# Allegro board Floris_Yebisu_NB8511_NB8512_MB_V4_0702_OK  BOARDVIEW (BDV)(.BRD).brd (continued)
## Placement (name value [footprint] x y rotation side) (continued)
DE3  WSB5524D  [NB_FBP1608_2_1D6X0D8X0D55]  187.81 20.19 270 top
DE5  RB500V-40  [NB_DIODE2_1D7X1D25X1_JX]  155.69 6.43 90 top
DE6  RB500V-40  [NB_DIODE2_1D7X1D25X1_JX]  155.71 15.1 270 top
DL2  PSBD2FD40V01  [NB_ESD2_1X0D6X0D4_JX]  154.68 26.74 270 top
DL3  PSBD2FD40V01  [NB_ESD2_1X0D6X0D4_JX]  156.87 23.8 0 top
DO1  RB521C30-2/TR  [NB_SOD-923_2_0D8X0D6X0D43]  132.94 6.91 270 top
DT1  RB521C30-2/TR  [NB_SOD-923_2_0D8X0D6X0D43]  27.25 36.47 180 bottom
DU1  LRB500V-40T1G  [NB_DIODE2_2D5X1D25X1_JX]  80.26 35.25 0 bottom
DU2  LRC  LBAT54CWT1  [SOT-323_3_2X1D25X1]  47.34 4.26 0 top
DU3  LRB500V-40T1G  [NB_DIODE2_2D5X1D25X1_JX]  43.99 6.33 0 top
DV1  LRB500V-40T1G  [NB_DIODE2_2D5X1D25X1_JX]  132.28 85.64 0 top
DV2  LRB500V-40T1G  [NB_DIODE2_2D5X1D25X1_JX]  129.11 85.63 0 top
DV3  LRB500V-40T1G  [NB_DIODE2_2D5X1D25X1_JX]  132.3 83.78 0 top
DV4  LRB500V-40T1G  [NB_DIODE2_2D5X1D25X1_JX]  129.11 83.78 0 top
DV5  LBAT54AWT1G  [NB_SOT323_2D4X2D2X1]  132.66 77.94 90 top
DV6  LRB500V-40T1G  [NB_DIODE2_2D5X1D25X1_JX]  133.29 80.06 0 top
DV7  LRB500V-40T1G  [NB_DIODE2_2D5X1D25X1_JX]  129.3 80.16 0 top
DV8  LBAT54AWT1G  [NB_SOT323_2D4X2D2X1]  129.28 77.57 90 top
DV9  LRC  LBAT54CWT1  [SOT-323_3_2X1D25X1]  138.37 54.75 0 bottom
DV11  LBAT54AWT1G  [NB_SOT323_2D4X2D2X1]  135.8 51.75 180 bottom
DV14  LRC  LBAT54CWT1  [SOT-323_3_2X1D25X1]  131.53 59.59 0 bottom
DV16  LRB500V-40T1G  [NB_DIODE2_2D5X1D25X1_JX]  132.54 62.02 180 bottom
DWC1  PSBD1DF40V3H  [DIODE_2D75X1D8X1D1]  114.68 6.3 0 bottom
DX1  LBAT54AWT1G  [NB_SOT323_2D4X2D2X1]  29.21 64.84 270 top
EDB3  PESD5V0F1BL  [TVS2_1D02X0D585X0D5]  20.8 38.22 90 top
EDB5  PESD5V0F1BL  [TVS2_1D02X0D585X0D5]  20.8 36.93 270 top
ESD1  ESD5342N-3/TR  [DFN1006_3_1X0D6X0D5_ESD5324N]  141.15 9.83 270 top
ESD2  ESD5342N-3/TR  [DFN1006_3_1X0D6X0D5_ESD5324N]  24.13 75.13 270 top
ESD3  ESD5342N-3/TR  [DFN1006_3_1X0D6X0D5_ESD5324N]  154.57 87.98 90 bottom
ESDB25  ESD9X7V-2/TR  [TVS_1X0D6X0D55]  19.23 41.36 90 bottom
ESDB34  LRC8804FDT1G  [NB_EMI10_2D5X1X0D65]  20.34 37.26 270 bottom
ESDE4  ESD5451R-2/TR  [TVS2_1X0D5X0D6]  56.26 9.98 90 bottom
ESDE5  ESD5451R-2/TR  [TVS2_1X0D5X0D6]  57.66 9.73 0 bottom
ESDE6  ESD5451R-2/TR  [TVS2_1X0D5X0D6]  67.44 6.04 270 top
ESDE7  ESD5451R-2/TR  [TVS2_1X0D5X0D6]  70.31 3.38 0 top
ESDE44  PESDTC5VB(BASIN)  [TVS2_1D01X0D61X0D4]  157.48 6.63 270 top
ESDE45  PESDTC5VB(BASIN)  [TVS2_1D01X0D61X0D4]  13.97 82.88 270 top
ESDI1  PESD5V0F1BL  [TVS2_1D02X0D585X0D5]  19.35 60.53 90 bottom
ESDI2  PESD5V0F1BL  [TVS2_1D02X0D585X0D5]  17.65 58.87 180 top
ESDI3  PESD5V0F1BL  [TVS2_1D02X0D585X0D5]  17.78 62.18 0 bottom
ESDI4  PESD5V0F1BL  [TVS2_1D02X0D585X0D5]  17.65 57.48 180 top
ESDI7  PESD5V0H1BSF  [NB_SOD962_0D625X0D325X0D32]  17.07 52.45 90 top
ESDI8  PESD5V0H1BSF  [NB_SOD962_0D625X0D325X0D32]  17.07 51.53 270 top
ESDI9  PESD5V0H1BSF  [NB_SOD962_0D625X0D325X0D32]  16.43 50.9 90 top
ESDI10  PESD5V0H1BSF  [NB_SOD962_0D625X0D325X0D32]  16.43 49.98 270 top
ESDI11  PESD5V0H1BSF  [NB_SOD962_0D625X0D325X0D32]  16.89 54.38 90 top
ESDI12  PESD5V0H1BSF  [NB_SOD962_0D625X0D325X0D32]  16.89 53.46 270 top
ESDI13  PESD5V0H1BSF  [NB_SOD962_0D625X0D325X0D32]  16.86 56.26 90 top
ESDI14  PESD5V0H1BSF  [NB_SOD962_0D625X0D325X0D32]  16.86 55.34 270 top
ESDL46  PESDTC5VB(BASIN)  [TVS2_1D01X0D61X0D4]  13.84 69.8 0 top
ESDT1  ESD5401N-2/TR  [NB_DIODE2_1D05X0D65X0D55]  10.41 14.42 270 top
ESDT2  PESD5V0H1BSF  [NB_SOD962_0D625X0D325X0D32]  14.1 23 90 top
ESDT3  PESD5V0H1BSF  [NB_SOD962_0D625X0D325X0D32]  14.1 21.98 270 top
ESDT4  PESD5V0H1BSF  [NB_SOD962_0D625X0D325X0D32]  14.1 23 90 bottom
ESDT5  PESD5V0H1BSF  [NB_SOD962_0D625X0D325X0D32]  14.1 21.98 270 bottom
ESDT6  ESD5342N-3/TR  [DFN1006_3_1X0D6X0D5_ESD5324N]  9.19 8.86 180 bottom
ESDT7  ESD5342N-3/TR  [DFN1006_3_1X0D6X0D5_ESD5324N]  7.77 10.64 270 bottom
ESDT8  PESD5V0H1BSF  [NB_SOD962_0D625X0D325X0D32]  13.84 16.96 270 bottom
ESDT9  PESD5V0H1BSF  [NB_SOD962_0D625X0D325X0D32]  13.84 17.86 90 bottom
ESDT10  PESD5V0H1BSF  [NB_SOD962_0D625X0D325X0D32]  13.84 16.96 270 top
ESDT11  PESD5V0H1BSF  [NB_SOD962_0D625X0D325X0D32]  13.84 17.86 90 top
ESDT12  PESD5V0F1BL  [TVS2_1D02X0D585X0D5]  11.43 19.12 270 top
ESDT13  PESD5V0F1BL  [TVS2_1D02X0D585X0D5]  11.43 20.52 90 top
ESDX1  ESD5451R-2/TR  [TVS2_1X0D5X0D6]  27.68 75.51 0 top
ESDX2  ESD5451R-2/TR  [TVS2_1X0D5X0D6]  26.16 75.26 180 top
FBA1  UPZ1608U331-1R5TF  [B0603_0D95]  173.14 35.38 270 top
FBA2  220ohm/100MHz,3000mA  [NB_B0805_1D05]  173.89 18.41 90 top
FBA4  BLM18PG181SN1D  [B0603_0D95]  185.42 30.05 0 top
FBA5  UPZ1608U331-1R5TF  [B0603_0D95]  164.74 30.6 0 top
FBE2  MMZ1005Y121C  [B0402_0D55]  170.69 15.57 180 top
FBI5  UPZ1608U331-1R5TF  [B0603_0D95]  27.94 58.11 180 bottom
FBT2  UPZ1608U331-1R5TF  [B0603_0D95]  29.82 30.55 270 bottom
GND_SPIO1  40MIL  [TPAD40-OP]  130.3 14.25 0 top
GPU_BOSS1  4.5*2.9-M2  [HOLE_3D5_5_T]  163.12 49.64 180 bottom
GPU_BOSS2  4.5*2.9-M2  [HOLE_3D5_5_T]  140.12 91.37 180 bottom
IOO1  40MIL  [TPAD40-OP]  129.23 12.77 90 top
IOO2  40MIL  [TPAD40-OP]  135.43 11.25 90 top
J1  AFC42-S06FMA-HF  [NB_CON6_5X3D05X1_0D5]  140.15 7.97 180 bottom
J3001  50208-00601-001  [NB_CON6_6D98X2D7X1D8_0D8]  133.48 6.68 180 bottom
JB8  C107PU-90939-L  [NB_USB9_16D37X13D1X7]  14.98 36.45 90 bottom
JDB1  FP225H-040610M  [NB_CON40_24D1X4D5X1D5_0D5]  185.11 42.45 270 bottom
JE3  50278-00401-003  [NB_CON4_10D15X4D5X1D9_1D25]  182.67 17.75 246.4 bottom
JE4  AFA01-S08FCA-00  [NB_CON8_12D7X5D8X3D6_1]  59.7 7.8 180 bottom
JE7  40542W90-28PN-SHL0ATCR  [NB_CON28_17D6X4D9X2_0D5]  164.15 8.1 180 bottom
JI1  HK01-07A821-01  [NB_HDMI23_15X13D85X6D95_CH178]  13.05 57 90 bottom
JKBL1  AFA01-S04F1A-00  [NB_CON4_8D9X5D35X2_1]  181.05 8.84 180 bottom
JKBL3  AFC42-S06FMA-HF  [NB_CON6_5X3D05X1_0D5]  150.15 88.03 0 bottom
JP2  AFC42-S04FKA-1H  [NB_CON4_4X3D05X1_0D5]  146.68 7.44 0 top
JRTCU1  50278-00201-001  [NB_CON2_7D65X5D5X1D9_1D25]  46.82 8.25 180 bottom
JSSD1  NASM0-S6701-TS20  [NB_NGFF75_21D9X6D4X2D65_M1]  26.8 3.67 180 bottom
JT1  40-42379-A0100RHF-HQ  [NB_TYPE_C24_8D94X8D45X3D74]  7.25 19.53 270 top
JW1  NASE0-S6701-TS20  [NB_NGFF75_21D85X6D4X2D3_0D5]  151.01 20.95 270 bottom
JX1  FP225H-040610M  [NB_CON40_24D1X4D5X1D5_0D5]  25.95 76.56 0 bottom
LEDE2  A-SP1942S1B1C  [NB_LED4_1D6X1D5X0D55]  180.59 5.36 90 top
LT1  LQM2MPNR68MGHL~~MPIE201610_R68M_LF~~WPN201610HR68MT  [L2016_1]  31.24 26.11 0 top
LT2  EXC14CE900U  [EMI_0D85X0D65X0D5]  12.83 19.82 270 top
LU1  HK1005R12J-T~~SDCL1005CR12JTF  [L0402]  61.47 49.11 90 top
LV1  BBPY00100505300Y00  [B0402_0D55]  134.49 57.6 90 top
LV3  BBPY00100505300Y00  [B0402_0D55]  159.22 87.24 180 bottom
MISOO1  40MIL  [TPAD40-OP]  129.18 10.89 90 top
MOSIO1  40MIL  [TPAD40-OP]  134.44 13.99 90 top
MR1  WH251E-3/TR  [NB_TSOT23_3_2D92X1D65X0D9]  2.84 92.48 270 top
NOREF  -  [unnamed]  5.15 10.77 0 top
NOREF#2  -  [unnamed]  9.65 70 0 top
NOREF#3  -  [unnamed#2]  189.86 10.36 0 top
NOREF#4  -  [unnamed]  185.9 95.96 270 top
NOREF#5  -  [unnamed#2]  189.25 93.29 0 top
NOREF#6  -  [#3]  56.38 37.97 0 top
NOREF#7  -  [unnamed#2]  10.95 83.59 0 top
NOREF#8  -  [unnamed#2]  189.86 10.36 180 bottom
NOREF#9  -  [unnamed#2]  189.25 93.29 180 bottom
NOREF#10  -  [unnamed#2]  3.48 91.03 180 bottom
PBTE1  C40_1  [TPC1]  162.96 25.42 0 top
PC1  CC0201KRX5R6BB473~~C0201X5R473K100NTA  [C0201]  132.33 81.37 90 top
PC101  C0603X5R106M250NTK~~CL10A106MA8NRNC~~GRM188R61E106MA73D~~TMK107BBJ106MA  [C0603_L]  47.5 23.7 180 bottom
PC102  C0201X5R104M250NTJ  [C0201]  42.23 14.6 270 bottom
PC103  C0201X5R104M250NTJ  [C0201]  41.67 15.11 90 bottom
PC104  C0201X5R104M250NTJ  [C0201]  41.67 14.09 270 bottom
PC105  C0201C0G101J500NTA~~GRM0335C1H101JA01D~~CC0201JRNPO9BN101  [C0201]  157.17 22.53 180 top
PC106  C0402X5R105K250NTB~~GRM155R61E105KA12D~~TMK105BJ105KV-F~~CL05A105KA5NQNC  [C0402]  83.82 8.23 270 bottom
PC107  C0402X5R105K250NTB~~GRM155R61E105KA12D~~TMK105BJ105KV-F~~CL05A105KA5NQNC  [C0402]  81.58 8.3 270 bottom
PC108  C0402X5R105K250NTB~~GRM155R61E105KA12D~~TMK105BJ105KV-F~~CL05A105KA5NQNC  [C0402]  75.31 21.41 180 bottom
PC109  C0201X5R104M250NTJ  [C0201]  76.71 22.04 90 bottom
PC110  C0603X5R106M250NTK~~CL10A106MA8NRNC~~GRM188R61E106MA73D~~TMK107BBJ106MA  [C0603_L]  47.5 20.9 180 top
PC111  LMK105BJ225MV-F~~CL05A225MP5NNNC~~GRM155R61A225ME95~~C0402X5R225M100NTB  [C0402_0D55]  45.73 18.62 90 bottom
PC112  C0201C0G101J250NTA+C0201C0G101J250NJA~~GRM0335C1E101JD01D~~CC0201JRNPO8BN101  [C0201]  50.56 10.49 270 bottom
PC113  0201X182M250NT~~C0201X5R182M250NTA~~ CC0201MRX5R8BB182  [C0201]  43.06 10.69 0 bottom
PC114  C0201C0G150J250NTA~~GRM0335C1E150JA01D~~CC0201JRNPO8BN150  [C0201]  43.01 12.52 180 bottom
PC115  C0201X7R681K160NTA//CC0201KRX7R8BB681~~C0201X7R681K160NTA  [C0201]  42.71 11.61 90 bottom
PC117  CC0201KRX5R8BB103+CC0201KRX7R8BB103~~C0201X5R103K250NTA~~0201X103K250NT  [C0201]  51.24 14.35 90 bottom
PC118  C0201C0G101J250NTA+C0201C0G101J250NJA~~GRM0335C1E101JD01D~~CC0201JRNPO8BN101  [C0201]  49.36 10.49 270 bottom
PC119  C0201X5R105M100NTX~~CL03A105MP3NSNC~~GRM033R61A105ME44//CL03A105MP3NSNC//C0201X5R105M100NTX//LMK063BBJ105MPLF~~LMK063BBJ105MPLF  [C0201_0D4]  51.06 11.3 270 bottom
PC120  C0201X7R151K250NTA~~GRM033R71E151KA01D~~CC0201KRX7R8BB151  [C0201]  44.96 18.74 270 bottom
PC121  CC0201KRX5R8BB103+CC0201KRX7R8BB103~~C0201X5R103K250NTA~~0201X103K250NT  [C0201]  50.71 14.93 90 bottom
PC122  C0603X5R106M250NTK~~CL10A106MA8NRNC~~GRM188R61E106MA73D~~TMK107BBJ106MA  [C0603_L]  47.5 22.3 180 top
PC123  CC0201KRX5R6BB473~~C0201X5R473K100NTA  [C0201]  43.18 18.23 270 bottom
PC124  CC0201KRX5R8BB103+CC0201KRX7R8BB103~~C0201X5R103K250NTA~~0201X103K250NT  [C0201]  53.17 17.09 90 bottom
PC125  CC0201JRX7R9BB102~~C0201X7R102J500NTA~~0201B102J500NT  [C0201]  15.31 76.65 180 top
PC126  C0201X5R104M250NTJ  [C0201]  20.5 72.31 0 top
PC127  CC0201KRX5R8BB103+CC0201KRX7R8BB103~~C0201X5R103K250NTA~~0201X103K250NT  [C0201]  51.24 15.42 270 bottom
PC128  C0402X5R105K250NTB~~GRM155R61E105KA12D~~TMK105BJ105KV-F~~CL05A105KA5NQNC  [C0402]  51.5 17.09 0 bottom
PC129  C0201X7R151K250NTA~~GRM033R71E151KA01D~~CC0201KRX7R8BB151  [C0201]  46.48 18.74 90 bottom
PC130  UMK105BJ102KV-F~~CC0402KRX7R9BB102~~0402B102K500~~C0402X7R102K500NTB~~GRM155R71H102KA01-(D/J)  [C0402_0D6]  65.4 22.17 0 bottom
PC131  CC0201KRX5R6BB473~~C0201X5R473K100NTA  [C0201]  47.12 18.74 90 bottom
PC132  C0603X5R475K250NTK~~CL10A475KA8NQNC~~GRM188R61E475KE15D~~TMK107BBJ475KA-T  [C0603]  20.19 73.2 0 top
PC133  C0201C0G101J500NTA~~GRM0335C1H101JA01D~~CC0201JRNPO9BN101  [C0201]  51.88 12.11 0 bottom
PC134  UMK105BJ102KV-F~~CC0402KRX7R9BB102~~0402B102K500~~C0402X7R102K500NTB~~GRM155R71H102KA01-(D/J)  [C0402_0D6]  68.58 22.17 180 bottom
PC135  TMK105CBJ225MV-F~~CL05A225MA5NUNC~~C0402X5R225M250NTN~~GRM155R61E225ME11D  [C0402_0D65]  19.3 82.37 90 top
PC136  C0402X5R105K250NTB~~GRM155R61E105KA12D~~TMK105BJ105KV-F~~CL05A105KA5NQNC  [C0402]  75.31 20.39 180 top
PC137  C0402X5R105K250NTB~~GRM155R61E105KA12D~~TMK105BJ105KV-F~~CL05A105KA5NQNC  [C0402]  75.31 19.38 180 bottom
PC138  C0402X5R105K250NTB~~GRM155R61E105KA12D~~TMK105BJ105KV-F~~CL05A105KA5NQNC  [C0402]  75.31 21.41 180 top
PC139  C0402X5R105K250NTB~~GRM155R61E105KA12D~~TMK105BJ105KV-F~~CL05A105KA5NQNC  [C0402]  75.31 19.38 180 top
PC140  C0402X5R105K250NTB~~GRM155R61E105KA12D~~TMK105BJ105KV-F~~CL05A105KA5NQNC  [C0402]  75.31 20.39 180 bottom
PC141  C0201C0G101J500NTA~~GRM0335C1H101JA01D~~CC0201JRNPO9BN101  [C0201]  46.86 10.49 270 bottom
PC142  C0201C0G101J500NTA~~GRM0335C1H101JA01D~~CC0201JRNPO9BN101  [C0201]  47.5 10.49 270 bottom
PC143  C0402X5R105K250NTB~~GRM155R61E105KA12D~~TMK105BJ105KV-F~~CL05A105KA5NQNC  [C0402]  84.71 8.23 270 bottom
PC144  C0603X5R106M250NTK~~CL10A106MA8NRNC~~GRM188R61E106MA73D~~TMK107BBJ106MA  [C0603_L]  47.5 20.9 180 bottom
PC145  C0603X5R106M250NTK~~CL10A106MA8NRNC~~GRM188R61E106MA73D~~TMK107BBJ106MA  [C0603_L]  47.5 22.3 180 bottom
PC146  C0603X5R106M250NTK~~CL10A106MA8NRNC~~GRM188R61E106MA73D~~TMK107BBJ106MA  [C0603_L]  47.5 23.7 180 top
PC150  CC0402KRX5R8BB104~~C0402X5R104M250NTN  [C0402]  25.7 67.92 0 top
PC151  CC0402KRX5R8BB104~~C0402X5R104M250NTN  [C0402]  21.74 67.56 270 top
PC152  C0201X5R104K6R3NTA+C0201X5R104K6R3NJA~~GRM033R60J104KE19D~~CC0201KRX5R5BB104  [C0201]  26.54 63.7 0 top
PC153  CC0402KRX5R8BB104~~C0402X5R104M250NTN  [C0402]  23.24 68.91 270 top
PC154  C0201C0G330J250NTA+C0201C0G330J250NJA~~GRM0335C1E330JD01~~CC0201JRNPO8BN330  [C0201]  44.94 10.54 270 bottom
PC155  C0201C0G101J500NTA~~GRM0335C1H101JA01D~~CC0201JRNPO9BN101  [C0201]  158.9 23.49 90 top
PC180  CC0201JRX7R9BB102~~C0201X7R102J500NTA~~0201B102J500NT  [C0201]  19.25 68.4 270 top
PC182  CC0402KRX5R8BB104~~C0402X5R104M250NTN  [C0402]  11.94 71.57 270 bottom
PC201  C0402X5R105K250NTB~~GRM155R61E105KA12D~~TMK105BJ105KV-F~~CL05A105KA5NQNC  [C0402]  51.81 47.57 90 top
PC204  C0201X5R104M250NTJ  [C0201]  51.05 47.6 90 top
PC205  CL10A226MQ8NRNC~~GRM188R60J226MEA0D~~JDK107BBJ226MA-T~~CC0603MRX5R5BB226  [C0603_L]  36.96 42.36 270 top
PC206  CC0201KRX5R7BB104~~C0201X5R104M160NTA  [C0201]  35.94 42.49 270 bottom
PC207  C0201X5R222K250NTA~~CC0201KRX5R8BB222  [C0201]  51.05 47.6 90 bottom
PC208  CL10A226MQ8NRNC~~GRM188R60J226MEA0D~~JDK107BBJ226MA-T~~CC0603MRX5R5BB226  [C0603_L]  36.96 42.36 270 bottom
PC209  CL10A226MQ8NRNC~~GRM188R60J226MEA0D~~JDK107BBJ226MA-T~~CC0603MRX5R5BB226  [C0603_L]  35.69 49.1 90 bottom
PC210  C0201X5R104K100NTA~~GRM033R61A104KE15D~~CC0201KRX5R6BB104  [C0201]  44.96 43.38 180 bottom
PC211  C0201C0G100J250NTA~~GRM0335C1E100JA01D~~CC0201JRNPO8BN100  [C0201]  47.27 42.77 0 bottom
PC213  CL10A226MQ8NRNC~~GRM188R60J226MEA0D~~JDK107BBJ226MA-T~~CC0603MRX5R5BB226  [C0603_L]  35.69 49.1 90 top
PC214  C0201X5R105M6R3NTX~~CL03A105MQ3CSNH~~GRM033R60J105MEA2D~~JMK063ABJ105MP+JDK063ABJ105MP~~CC0201MRX5R5BB105  [C0201_0D4]  48.87 44.14 270 bottom
PC215  C0402X5R475M6R3NTC~~JMK105BBJ475MV-F+JDK105ABJ475MV~~CC0402MRX5R5BB475~~CL05A475MQ5NRNC~~GRM155R60J475ME87D  [C0402_0D65]  47.75 43.89 270 bottom
PC216  CC0201KRX5R7BB104~~C0201X5R104M160NTA  [C0201]  51.05 44.02 270 bottom
PC220  C0402X5R105K250NTB~~GRM155R61E105KA12D~~TMK105BJ105KV-F~~CL05A105KA5NQNC  [C0402]  51.81 47.57 90 bottom
PC301  C0402X5R105K250NTB~~GRM155R61E105KA12D~~TMK105BJ105KV-F~~CL05A105KA5NQNC  [C0402]  52.04 55.29 90 bottom
PC302  C0402X5R105K250NTB~~GRM155R61E105KA12D~~TMK105BJ105KV-F~~CL05A105KA5NQNC  [C0402]  52.04 55.29 90 top
PC305  C0201X5R104M250NTJ  [C0201]  51.28 55.29 90 bottom
PC306  C0201X5R222K250NTA~~CC0201KRX5R8BB222  [C0201]  51.28 55.29 90 top
PC308  C0201X5R104K100NTA~~GRM033R61A104KE15D~~CC0201KRX5R6BB104  [C0201]  45.57 51.71 90 bottom
PC309  C0201X5R105M6R3NTX~~CL03A105MQ3CSNH~~GRM033R60J105MEA2D~~JMK063ABJ105MP+JDK063ABJ105MP~~CC0201MRX5R5BB105  [C0201_0D4]  47.6 51.89 270 bottom
PC310  CL10A226MQ8NRNC~~GRM188R60J226MEA0D~~JDK107BBJ226MA-T~~CC0603MRX5R5BB226  [C0603_L]  34.23 58.01 90 bottom
PC311  CL10A226MQ8NRNC~~GRM188R60J226MEA0D~~JDK107BBJ226MA-T~~CC0603MRX5R5BB226  [C0603_L]  35.65 57.98 90 bottom
PC312  CL10A226MQ8NRNC~~GRM188R60J226MEA0D~~JDK107BBJ226MA-T~~CC0603MRX5R5BB226  [C0603_L]  35.74 52.42 270 bottom
PC313  CL10A226MQ8NRNC~~GRM188R60J226MEA0D~~JDK107BBJ226MA-T~~CC0603MRX5R5BB226  [C0603_L]  34.24 58.01 90 top
PC314  CL10A226MQ8NRNC~~GRM188R60J226MEA0D~~JDK107BBJ226MA-T~~CC0603MRX5R5BB226  [C0603_L]  35.65 57.98 90 top
PC316  CL10A226MQ8NRNC~~GRM188R60J226MEA0D~~JDK107BBJ226MA-T~~CC0603MRX5R5BB226  [C0603_L]  35.73 52.42 270 top
PC317  CC0201KRX5R7BB104~~C0201X5R104M160NTA  [C0201]  34.75 52.27 270 top
PC318  C0201C0G100J250NTA~~GRM0335C1E100JA01D~~CC0201JRNPO8BN100  [C0201]  49.27 51.66 180 bottom
PC319  C0201X5R105M6R3NTX~~CL03A105MQ3CSNH~~GRM033R60J105MEA2D~~JMK063ABJ105MP+JDK063ABJ105MP~~CC0201MRX5R5BB105  [C0201_0D4]  48.16 51.89 270 bottom
PC320  CAP  [C0201]  49.27 51.13 0 bottom
PC401  CC0201KRX5R7BB104~~C0201X5R104M160NTA  [C0201]  37.72 61.54 90 bottom
PC402  CL10A226MQ8NRNC~~GRM188R60J226MEA0D~~JDK107BBJ226MA-T~~CC0603MRX5R5BB226  [C0603_L]  45.67 62.56 0 bottom
PC403  C0603X5R106M6R3NTK~~CL10A106MQ8NNNC~~GRM188R60J106ME47D~~JMK107BJ106MA-T  [C0603_L]  41.5 63.07 90 bottom
PC404  CC0201KRX5R7BB104~~C0201X5R104M160NTA  [C0201]  36.83 59.76 0 bottom
PC405  CC0201JRNPO8BN220~~GRM0335C1E220JD01  [C0201]  37.59 60.02 90 bottom
PC406  CL10A226MQ8NRNC~~GRM188R60J226MEA0D~~JDK107BBJ226MA-T~~CC0603MRX5R5BB226  [C0603_L]  45.67 62.56 0 top
PC410  CL10A226MQ8NRNC~~GRM188R60J226MEA0D~~JDK107BBJ226MA-T~~CC0603MRX5R5BB226  [C0603_L]  30.86 58.62 0 top
PC411  C0603X5R106M6R3NTK~~CL10A106MQ8NNNC~~GRM188R60J106ME47D~~JMK107BJ106MA-T  [C0603_L]  29.59 63.57 180 bottom
PC412  CC0201JRNPO8BN220~~GRM0335C1E220JD01  [C0201]  35.81 63.32 0 bottom
PC413  CL10A226MQ8NRNC~~GRM188R60J226MEA0D~~JDK107BBJ226MA-T~~CC0603MRX5R5BB226  [C0603_L]  30.86 58.62 0 bottom
PC414  CC0201KRX5R7BB104~~C0201X5R104M160NTA  [C0201]  30.99 57.6 0 bottom
PC415  CC0201KRX5R7BB104~~C0201X5R104M160NTA  [C0201]  35.43 61.67 270 bottom
PC501  C0201X5R104K100NTA~~GRM033R61A104KE15D~~CC0201KRX5R6BB104  [C0201]  78.1 23.04 90 bottom
PC502  C0201X5R104M250NTJ  [C0201]  74.8 29.66 90 bottom
PC503  C0201X5R105M6R3NTX~~CL03A105MQ3CSNH~~GRM033R60J105MEA2D~~JMK063ABJ105MP+JDK063ABJ105MP~~CC0201MRX5R5BB105  [C0201_0D4]  73.4 24.2 180 bottom
PC504  CC0402KRX5R8BB104~~C0402X5R104M250NTN  [C0402]  88.21 29.92 0 top
PC505  CC0402KRX5R8BB104~~C0402X5R104M250NTN  [C0402]  80.26 30.05 270 top
PC506  CAP  [C0201]  73.66 28.27 90 bottom
PC507  CC0201KBX7R8BB821~~C0201X7R821K250NTA//CC0201KBX7R8BB821  [C0201]  79.88 29.28 0 bottom
PC508  C0201X7R271K500NTA~~CC0201KRX7R9BB271  [C0201]  79.88 27.76 0 bottom
PC509  C0201C0G150J250NTA~~GRM0335C1E150JA01D~~CC0201JRNPO8BN150  [C0201]  78.99 29.03 270 bottom
PC510  C0201X5R104K100NTA~~GRM033R61A104KE15D~~CC0201KRX5R6BB104  [C0201]  81.66 28.27 180 bottom
PC511  CL10A226MQ8NRNC~~GRM188R60J226MEA0D~~JDK107BBJ226MA-T~~CC0603MRX5R5BB226  [C0603_L]  88.26 32.53 180 bottom
PC512  CL10A226MQ8NRNC~~GRM188R60J226MEA0D~~JDK107BBJ226MA-T~~CC0603MRX5R5BB226  [C0603_L]  88.26 31.06 180 bottom
PC513  CL10A226MQ8NRNC~~GRM188R60J226MEA0D~~JDK107BBJ226MA-T~~CC0603MRX5R5BB226  [C0603_L]  97.15 30.12 0 top
PC514  CL10A226MQ8NRNC~~GRM188R60J226MEA0D~~JDK107BBJ226MA-T~~CC0603MRX5R5BB226  [C0603_L]  88.26 29.54 180 bottom
PC515  CL10A226MQ8NRNC~~GRM188R60J226MEA0D~~JDK107BBJ226MA-T~~CC0603MRX5R5BB226  [C0603_L]  88.26 32.53 180 top
PC516  CL10A226MQ8NRNC~~GRM188R60J226MEA0D~~JDK107BBJ226MA-T~~CC0603MRX5R5BB226  [C0603_L]  88.26 31.06 180 top
PC517  C0402X5R105K250NTB~~GRM155R61E105KA12D~~TMK105BJ105KV-F~~CL05A105KA5NQNC  [C0402]  87.88 22.04 90 bottom
PC518  C0402X5R105K250NTB~~GRM155R61E105KA12D~~TMK105BJ105KV-F~~CL05A105KA5NQNC  [C0402]  87.88 22.04 90 top
PC519  C0402X5R105K250NTB~~GRM155R61E105KA12D~~TMK105BJ105KV-F~~CL05A105KA5NQNC  [C0402]  86.99 22.04 90 top
PC520  C0402X5R105K250NTB~~GRM155R61E105KA12D~~TMK105BJ105KV-F~~CL05A105KA5NQNC  [C0402]  86.99 22.04 90 bottom
PC521  CC0201JRX7R9BB102~~C0201X7R102J500NTA~~0201B102J500NT  [C0201]  86.1 22.02 90 bottom
PC522  C0201X5R104M250NTJ  [C0201]  86.1 22.02 90 top
PC530  C0201X5R104K6R3NTA+C0201X5R104K6R3NJA~~GRM033R60J104KE19D~~CC0201KRX5R5BB104  [C0201]  81.41 28.52 270 top
PC601  C0201X5R104M250NTJ  [C0201]  107.69 17.22 270 bottom
PC602  C0402X5R475M6R3NTC~~JMK105BBJ475MV-F+JDK105ABJ475MV~~CC0402MRX5R5BB475~~CL05A475MQ5NRNC~~GRM155R60J475ME87D  [C0402_0D65]  99.5 25.6 180 top
PC603  C0201X5R105M6R3NTX~~CL03A105MQ3CSNH~~GRM033R60J105MEA2D~~JMK063ABJ105MP+JDK063ABJ105MP~~CC0201MRX5R5BB105  [C0201_0D4]  108.46 17.22 90 bottom
PC604  LMK105BJ225MV-F~~CL05A225MP5NNNC~~GRM155R61A225ME95~~C0402X5R225M100NTB  [C0402_0D55]  108.84 21.96 0 top
PC605  C0201X5R104K100NTA~~GRM033R61A104KE15D~~CC0201KRX5R6BB104  [C0201]  108.96 20.9 90 top
PC606  GRM155R61A474KE15D~~C0402X5R474K100NTN~~LMK105BJ474KV-F~~CC0402KRX5R6BB474  [C0402_0D6]  99.44 22.55 0 bottom
PC607  C0201X5R104M250NTJ  [C0201]  101.09 27.38 270 top
PC608  C0201C0G101J500NTA~~GRM0335C1H101JA01D~~CC0201JRNPO9BN101  [C0201]  101.22 19.12 0 top
PC609  C0201X7R221K500NTA~~GRM033R71H221KA12D~~CC0201KRX7R9BB221  [C0201]  100.18 18.49 180 bottom
PC611  GRM155R71H332KA01-D/J~~C0402X7R332K500NY~~UMK105BJ332KV-F~~CC0402KRX7R9BB332  [C0402_0D6]  132.46 23.58 270 top
PC612  C0402X5R104K100NTB~~GRM155R71A104KA01-(D/J)~~LMK105BJ104KV-F~~CC0402KRX5R6BB104~~0402X104K100  [C0402_0D6]  106.81 17.22 270 top
PC613  C0402X5R104K100NTB~~GRM155R71A104KA01-(D/J)~~LMK105BJ104KV-F~~CC0402KRX5R6BB104~~0402X104K100  [C0402_0D6]  103.38 15.82 180 top
PC615  GRM155R71H332KA01-D/J~~C0402X7R332K500NY~~UMK105BJ332KV-F~~CC0402KRX7R9BB332  [C0402_0D6]  112.27 12.24 0 bottom
PC616  C0402X5R104K100NTB~~GRM155R71A104KA01-(D/J)~~LMK105BJ104KV-F~~CC0402KRX5R6BB104~~0402X104K100  [C0402_0D6]  103.25 17.22 270 top
PC617  C0402X5R104K100NTB~~GRM155R71A104KA01-(D/J)~~LMK105BJ104KV-F~~CC0402KRX5R6BB104~~0402X104K100  [C0402_0D6]  105.66 15.06 0 top
PC618  C0201X5R104M250NTJ  [C0201]  123.77 15.24 0 top
PC619  CC0201JRX7R9BB102~~C0201X7R102J500NTA~~0201B102J500NT  [C0201]  123.7 15.24 0 bottom
PC620  C0402X5R105K250NTB~~GRM155R61E105KA12D~~TMK105BJ105KV-F~~CL05A105KA5NQNC  [C0402]  123.72 13.66 0 top
PC621  C0201X5R104K100NTA~~GRM033R61A104KE15D~~CC0201KRX5R6BB104  [C0201]  111 25.85 0 top
PC622  C0402X5R105K250NTB~~GRM155R61E105KA12D~~TMK105BJ105KV-F~~CL05A105KA5NQNC  [C0402]  123.72 14.55 0 bottom
PC623  C0402X5R105K250NTB~~GRM155R61E105KA12D~~TMK105BJ105KV-F~~CL05A105KA5NQNC  [C0402]  123.72 13.66 0 bottom
PC624  C0402X5R105K250NTB~~GRM155R61E105KA12D~~TMK105BJ105KV-F~~CL05A105KA5NQNC  [C0402]  123.72 14.55 0 top
PC625  C0402X5R105K250NTB~~GRM155R61E105KA12D~~TMK105BJ105KV-F~~CL05A105KA5NQNC  [C0402]  116.46 14.02 180 bottom
PC626  C0402X5R105K250NTB~~GRM155R61E105KA12D~~TMK105BJ105KV-F~~CL05A105KA5NQNC  [C0402]  116.46 14.02 180 top
PC627  C0402X5R105K250NTB~~GRM155R61E105KA12D~~TMK105BJ105KV-F~~CL05A105KA5NQNC  [C0402]  116.46 13.15 180 bottom
PC628  C0402X5R105K250NTB~~GRM155R61E105KA12D~~TMK105BJ105KV-F~~CL05A105KA5NQNC  [C0402]  116.46 13.15 180 top
PC629  C0201X5R104M250NTJ  [C0201]  116.46 14.7 180 top
PC630  CC0201JRX7R9BB102~~C0201X7R102J500NTA~~0201B102J500NT  [C0201]  116.46 14.7 180 bottom
PC631  C0201X5R104K6R3NTA+C0201X5R104K6R3NJA~~GRM033R60J104KE19D~~CC0201KRX5R5BB104  [C0201]  101.22 21.13 180 top
PC640  C0201X5R104K6R3NTA+C0201X5R104K6R3NJA~~GRM033R60J104KE19D~~CC0201KRX5R5BB104  [C0201]  99.9 19.38 90 top
PC641  C0201X5R104K6R3NTA+C0201X5R104K6R3NJA~~GRM033R60J104KE19D~~CC0201KRX5R5BB104  [C0201]  101.22 21.87 180 top
PC656  C0201X5R105M6R3NTX~~CL03A105MQ3CSNH~~GRM033R60J105MEA2D~~JMK063ABJ105MP+JDK063ABJ105MP~~CC0201MRX5R5BB105  [C0201_0D4]  105.56 28.57 180 top
PC657  C0201C0G2R2C500NTA~~GRM0335C1H2R2CA01D~~CC0201CRNPO9BN2R2  [C0201]  105.51 27.4 270 top
PC658  C0201C0G2R2C500NTA~~GRM0335C1H2R2CA01D~~CC0201CRNPO9BN2R2  [C0201]  106.53 27.4 270 top
PC659  C0201C0G2R2C500NTA~~GRM0335C1H2R2CA01D~~CC0201CRNPO9BN2R2  [C0201]  108.41 27.86 180 top
PC701  C0201X5R474M6R3NTJ~~GRM033R60J474ME90D~~CC0201MRX5R5BB474  [C0201]  44.09 78.1 180 bottom
PC702  C0201X5R104K100NTA~~GRM033R61A104KE15D~~CC0201KRX5R6BB104  [C0201]  51.2 78.51 0 bottom
PC703  C0402X5R106M6R3NTC~~CL05A106MQ5NUNC~~GRM155R60J106ME44~~JMK105CBJ106MV-F  [C0402_0D8]  44.6 84.5 180 bottom
PC704  C0402X5R105K250NTB~~GRM155R61E105KA12D~~TMK105BJ105KV-F~~CL05A105KA5NQNC  [C0402]  43.15 80.95 90 top
PC705  C0402X5R105K250NTB~~GRM155R61E105KA12D~~TMK105BJ105KV-F~~CL05A105KA5NQNC  [C0402]  43.15 80.95 90 bottom
PC708  CL10A226MQ8NRNC~~GRM188R60J226MEA0D~~JDK107BBJ226MA-T~~CC0603MRX5R5BB226  [C0603_L]  50.39 91.41 180 bottom
PC709  CL10A226MQ8NRNC~~GRM188R60J226MEA0D~~JDK107BBJ226MA-T~~CC0603MRX5R5BB226  [C0603_L]  50.39 88.67 180 top
PC710  CL10A226MQ8NRNC~~GRM188R60J226MEA0D~~JDK107BBJ226MA-T~~CC0603MRX5R5BB226  [C0603_L]  50.39 91.41 180 top
PC711  CL10A226MQ8NRNC~~GRM188R60J226MEA0D~~JDK107BBJ226MA-T~~CC0603MRX5R5BB226  [C0603_L]  50.39 88.67 180 bottom
PC712  CL10A226MQ8NRNC~~GRM188R60J226MEA0D~~JDK107BBJ226MA-T~~CC0603MRX5R5BB226  [C0603_L]  50.39 90.04 180 top
PC714  CL10A226MQ8NRNC~~GRM188R60J226MEA0D~~JDK107BBJ226MA-T~~CC0603MRX5R5BB226  [C0603_L]  50.39 90.04 180 bottom
PC715  C0402X5R106M6R3NTC~~CL05A106MQ5NUNC~~GRM155R60J106ME44~~JMK105CBJ106MV-F  [C0402_0D8]  47.01 79.14 180 top
PC716  C0201X5R105M6R3NTX~~CL03A105MQ3CSNH~~GRM033R60J105MEA2D~~JMK063ABJ105MP+JDK063ABJ105MP~~CC0201MRX5R5BB105  [C0201_0D4]  44.65 83.18 180 bottom
PC717  CL10A226MQ8NRNC~~GRM188R60J226MEA0D~~JDK107BBJ226MA-T~~CC0603MRX5R5BB226  [C0603_L]  46.28 87.2 180 bottom
PC718  CL10A226MQ8NRNC~~GRM188R60J226MEA0D~~JDK107BBJ226MA-T~~CC0603MRX5R5BB226  [C0603_L]  46.28 87.2 180 top
PC719  C0402X5R106M6R3NTC~~CL05A106MQ5NUNC~~GRM155R60J106ME44~~JMK105CBJ106MV-F  [C0402_0D8]  47.04 76.88 270 bottom
PC720  C0201X5R104K6R3NTA+C0201X5R104K6R3NJA~~GRM033R60J104KE19D~~CC0201KRX5R5BB104  [C0201]  45.59 83.36 180 top
PC721  C0201X5R104K6R3NTA+C0201X5R104K6R3NJA~~GRM033R60J104KE19D~~CC0201KRX5R5BB104  [C0201]  44.65 83.72 180 bottom
PC730  C0201X5R104M250NTJ  [C0201]  44.35 80.85 90 top
PC818  C0201X5R104K100NTA~~GRM033R61A104KE15D~~CC0201KRX5R6BB104  [C0201]  163.57 44.02 270 bottom
PC819  C0402X5R105K250NTB~~GRM155R61E105KA12D~~TMK105BJ105KV-F~~CL05A105KA5NQNC  [C0402]  157.73 44.78 270 top
PC820  C0402X5R105K250NTB~~GRM155R61E105KA12D~~TMK105BJ105KV-F~~CL05A105KA5NQNC  [C0402]  157.73 44.78 270 bottom
PC821  C0201X5R104M250NTJ  [C0201]  156.97 44.78 270 bottom
PC822  CC0201JRX7R9BB102~~C0201X7R102J500NTA~~0201B102J500NT  [C0201]  156.97 44.78 270 top
PC823  C0201X5R104M250NTJ  [C0201]  165.95 37.02 180 bottom
PC824  GRM155R60J225KE95~~CL05A225KQ5NNNC  [C0402]  161.88 40.45 180 bottom
PC825  C0402X5R105K250NTB~~GRM155R61E105KA12D~~TMK105BJ105KV-F~~CL05A105KA5NQNC  [C0402]  170.4 39.45 0 bottom
PC827  C0201X5R104M250NTJ  [C0201]  167.04 43.85 0 bottom
PC828  C0201C0G100J250NTA~~GRM0335C1E100JA01D~~CC0201JRNPO8BN100  [C0201]  167.84 44.13 90 bottom
PC830  GRM155R71H332KA01-D/J~~C0402X7R332K500NY~~UMK105BJ332KV-F~~CC0402KRX7R9BB332  [C0402_0D6]  150.26 43.56 180 top
PC833  CL10A226MQ8NRNC~~GRM188R60J226MEA0D~~JDK107BBJ226MA-T~~CC0603MRX5R5BB226  [C0603_L]  138.3 48.71 90 bottom
PC834  CL10A226MQ8NRNC~~GRM188R60J226MEA0D~~JDK107BBJ226MA-T~~CC0603MRX5R5BB226  [C0603_L]  139.95 48.71 90 top
PC836  C0603X5R106M6R3NTK~~CL10A106MQ8NNNC~~GRM188R60J106ME47D~~JMK107BJ106MA-T  [C0603_L]  138.3 48.71 90 top
PC837  C0603X5R106M6R3NTK~~CL10A106MQ8NNNC~~GRM188R60J106ME47D~~JMK107BJ106MA-T  [C0603_L]  139.95 48.71 90 bottom
PC844  C0201X5R223K6R3NTA~~GRM033R60J223KE01D~~CC0201KRX5R5BB223  [C0201]  170.21 41.45 180 bottom
PC855  GRM155R71H332KA01-D/J~~C0402X7R332K500NY~~UMK105BJ332KV-F~~CC0402KRX7R9BB332  [C0402_0D6]  150.26 40.66 180 top
PC856  C0201X5R104K100NTA~~GRM033R61A104KE15D~~CC0201KRX5R6BB104  [C0201]  161.66 39.21 0 bottom
PC857  C0402X5R105K250NTB~~GRM155R61E105KA12D~~TMK105BJ105KV-F~~CL05A105KA5NQNC  [C0402]  157.73 39.19 90 top
PC858  C0402X5R105K250NTB~~GRM155R61E105KA12D~~TMK105BJ105KV-F~~CL05A105KA5NQNC  [C0402]  157.73 39.19 90 bottom
PC859  CC0201JRX7R9BB102~~C0201X7R102J500NTA~~0201B102J500NT  [C0201]  156.97 39.11 90 top
PC860  C0201X5R104M250NTJ  [C0201]  156.97 39.11 90 bottom
PC863  CC0201JRX7R9BB102~~C0201X7R102J500NTA~~0201B102J500NT  [C0201]  166.98 35.99 0 bottom
PC864  C0201C0G101J250NTA+C0201C0G101J250NJA~~GRM0335C1E101JD01D~~CC0201JRNPO8BN101  [C0201]  150.42 42.24 270 bottom
PC865  C0201C0G101J250NTA+C0201C0G101J250NJA~~GRM0335C1E101JD01D~~CC0201JRNPO8BN101  [C0201]  156.46 40.59 0 bottom
PC867  C0201X7R472K100NTA+C0201X7R472K100NJA~~GRM033R71A472KA01D~~CC0201KRX7R6BB472  [C0201]  169.98 44.11 0 bottom
PC868  CC0201KRX5R7BB104~~C0201X5R104M160NTA  [C0201]  171.04 42.79 90 bottom
PC887  CC0201JRX7R9BB102~~C0201X7R102J500NTA~~0201B102J500NT  [C0201]  167.25 36.76 270 bottom
PC888  CC0201JRX7R9BB102~~C0201X7R102J500NTA~~0201B102J500NT  [C0201]  170.05 36.26 90 bottom
PC901  C0402X5R106M6R3NTC~~CL05A106MQ5NUNC~~GRM155R60J106ME44~~JMK105CBJ106MV-F  [C0402_0D8]  46.68 66.47 180 top
PC902  C0201X5R105M6R3NTX~~CL03A105MQ3CSNH~~GRM033R60J105MEA2D~~JMK063ABJ105MP+JDK063ABJ105MP~~CC0201MRX5R5BB105  [C0201_0D4]  43.08 63.42 180 bottom
PC903  C0201X5R105M6R3NTX~~CL03A105MQ3CSNH~~GRM033R60J105MEA2D~~JMK063ABJ105MP+JDK063ABJ105MP~~CC0201MRX5R5BB105  [C0201_0D4]  40.38 64.54 270 bottom
PC904  CAP  [C0201]  39.83 64.54 270 bottom
PC905  C0201X5R105M6R3NTX~~CL03A105MQ3CSNH~~GRM033R60J105MEA2D~~JMK063ABJ105MP+JDK063ABJ105MP~~CC0201MRX5R5BB105  [C0201_0D4]  46.73 68.65 180 top
PC906  C0201X5R105M6R3NTX~~CL03A105MQ3CSNH~~GRM033R60J105MEA2D~~JMK063ABJ105MP+JDK063ABJ105MP~~CC0201MRX5R5BB105  [C0201_0D4]  40.08 73.63 180 bottom
PC907  C0201X5R105M6R3NTX~~CL03A105MQ3CSNH~~GRM033R60J105MEA2D~~JMK063ABJ105MP+JDK063ABJ105MP~~CC0201MRX5R5BB105  [C0201_0D4]  43.28 68.5 0 bottom
PC908  CAP  [C0201]  43.28 69.06 0 bottom
PC909  C0201X5R105M6R3NTX~~CL03A105MQ3CSNH~~GRM033R60J105MEA2D~~JMK063ABJ105MP+JDK063ABJ105MP~~CC0201MRX5R5BB105  [C0201_0D4]  27.53 46.5 0 bottom
PC910  C0402X5R106M6R3NTC~~CL05A106MQ5NUNC~~GRM155R60J106ME44~~JMK105CBJ106MV-F  [C0402_0D8]  27.56 45.79 0 bottom
PC911  CAP  [C0201]  18.79 46.81 180 bottom
PC912  C0201X5R222K250NTA~~CC0201KRX5R8BB222  [C0201]  19.43 44.65 180 bottom
PC913  C0402X5R106M6R3NTC~~CL05A106MQ5NUNC~~GRM155R60J106ME44~~JMK105CBJ106MV-F  [C0402_0D8]  24.76 41.35 270 bottom
PC914  CC0201JRX7R9BB102~~C0201X7R102J500NTA~~0201B102J500NT  [C0201]  19.43 45.16 180 bottom
PC915  CAP  [C0201]  19.43 44.14 180 bottom
PC916  CC0201KRX5R7BB104~~C0201X5R104M160NTA  [C0201]  50.39 59.1 270 bottom
PC930  GRM155R61C105KA12~~CL05A105KO5NNNC~~C0402X5R105K160NTB  [C0402]  188.59 23.81 90 top
PC931  C0402X5R106M6R3NTC~~CL05A106MQ5NUNC~~GRM155R60J106ME44~~JMK105CBJ106MV-F  [C0402_0D8]  187.7 25.09 0 top
PC932  CAP  [C0201]  187.63 24.2 0 top
PC969  C0201X5R105M6R3NTX~~CL03A105MQ3CSNH~~GRM033R60J105MEA2D~~JMK063ABJ105MP+JDK063ABJ105MP~~CC0201MRX5R5BB105  [C0201_0D4]  50.9 68.81 0 bottom
PC970  C0201X5R105M6R3NTX~~CL03A105MQ3CSNH~~GRM033R60J105MEA2D~~JMK063ABJ105MP+JDK063ABJ105MP~~CC0201MRX5R5BB105  [C0201_0D4]  39.72 66.19 180 bottom
PC971  C0201X5R105M6R3NTX~~CL03A105MQ3CSNH~~GRM033R60J105MEA2D~~JMK063ABJ105MP+JDK063ABJ105MP~~CC0201MRX5R5BB105  [C0201_0D4]  39.72 68.22 180 bottom
PC972  C0201X5R105M6R3NTX~~CL03A105MQ3CSNH~~GRM033R60J105MEA2D~~JMK063ABJ105MP+JDK063ABJ105MP~~CC0201MRX5R5BB105  [C0201_0D4]  50.95 65.2 0 bottom
PC975  CC0201KRX5R7BB104~~C0201X5R104M160NTA  [C0201]  51.26 67.13 90 bottom
PC976  CC0201KRX5R7BB104~~C0201X5R104M160NTA  [C0201]  39.72 67.71 180 bottom
PC977  CC0201KRX5R7BB104~~C0201X5R104M160NTA  [C0201]  50.95 63.22 0 bottom
PC978  CC0201KRX5R7BB104~~C0201X5R104M160NTA  [C0201]  38.1 70.69 180 bottom
PC1101  C0201X5R104K100NTA~~GRM033R61A104KE15D~~CC0201KRX5R6BB104  [C0201]  180.29 39.39 90 bottom
PC1102  CL05A225MQ5NNNC~~GRM155R60J225ME15D~~JMK105 BJ225MV-F~~CC0402MRX5R5BB225~~C0402X5R225M6R3NTB  [C0402]  172.93 40.77 90 bottom
PC1103  C0402X5R105K250NTB~~GRM155R61E105KA12D~~TMK105BJ105KV-F~~CL05A105KA5NQNC  [C0402]  179.83 36.4 270 bottom
PC1104  C0201X5R104M250NTJ  [C0201]  178.81 36.4 270 bottom
PC1105  C0201X5R222K250NTA~~CC0201KRX5R8BB222  [C0201]  178.81 36.4 270 top
PC1106  C0402X5R105K250NTB~~GRM155R61E105KA12D~~TMK105BJ105KV-F~~CL05A105KA5NQNC  [C0402]  179.83 36.4 270 top
PC1107  C0201X5R104K6R3NTA+C0201X5R104K6R3NJA~~GRM033R60J104KE19D~~CC0201KRX5R5BB104  [C0201]  173.39 35.18 270 bottom
PC1108  C0201X5R105M6R3NTX~~CL03A105MQ3CSNH~~GRM033R60J105MEA2D~~JMK063ABJ105MP+JDK063ABJ105MP~~CC0201MRX5R5BB105  [C0201_0D4]  172.97 38.81 180 bottom
PC1109  CL10A226MQ8NRNC~~GRM188R60J226MEA0D~~JDK107BBJ226MA-T~~CC0603MRX5R5BB226  [C0603_L]  174.34 49.45 180 bottom
PC1110  CL10A226MQ8NRNC~~GRM188R60J226MEA0D~~JDK107BBJ226MA-T~~CC0603MRX5R5BB226  [C0603_L]  174.34 49.45 180 top
PC1120  CL10A226MQ8NRNC~~GRM188R60J226MEA0D~~JDK107BBJ226MA-T~~CC0603MRX5R5BB226  [C0603_L]  179.58 49.4 0 top
PC1121  CL10A226MQ8NRNC~~GRM188R60J226MEA0D~~JDK107BBJ226MA-T~~CC0603MRX5R5BB226  [C0603_L]  179.58 50.77 0 bottom
PC1122  CL10A226MQ8NRNC~~GRM188R60J226MEA0D~~JDK107BBJ226MA-T~~CC0603MRX5R5BB226  [C0603_L]  179.58 50.77 0 top
PC1123  C0201X7R222K160NTA~~GRM033R71C222KA88D~~CC0201KRX7R7BB222  [C0201]  174.38 50.49 180 top
PC1124  CL10A226MQ8NRNC~~GRM188R60J226MEA0D~~JDK107BBJ226MA-T~~CC0603MRX5R5BB226  [C0603_L]  179.58 49.4 0 bottom
PC1150  0201WMF1001TCE+0201WMF1001TEE~~MCR006YRTF1001~~RC0201FR-071KL~~WR02X1001FAL  [R0201]  172.32 37.69 180 bottom
PC1201  C0201X5R105M6R3NTX~~CL03A105MQ3CSNH~~GRM033R60J105MEA2D~~JMK063ABJ105MP+JDK063ABJ105MP~~CC0201MRX5R5BB105  [C0201_0D4]  129.84 88.95 180 bottom
PC1202  C0402X5R106M6R3NTC~~CL05A106MQ5NUNC~~GRM155R60J106ME44~~JMK105CBJ106MV-F  [C0402_0D8]  134.84 89.01 0 bottom
PC1203  C0402X5R106M6R3NTC~~CL05A106MQ5NUNC~~GRM155R60J106ME44~~JMK105CBJ106MV-F  [C0402_0D8]  136.09 94.41 90 bottom
PC1204  C0201X5R104M6R3NTA~~0201X104M6R3NT  [C0201]  134.77 89.83 0 bottom
PC1205  C0201X5R105M6R3NTX~~CL03A105MQ3CSNH~~GRM033R60J105MEA2D~~JMK063ABJ105MP+JDK063ABJ105MP~~CC0201MRX5R5BB105  [C0201_0D4]  134.72 95.02 0 bottom
PC1208  C0201X5R104M6R3NTA~~0201X104M6R3NT  [C0201]  134.67 91.54 0 bottom
PC1209  C0201X7R102K250NTA+C0201X7R102K250NJA~~GRM033R71E102KA01D~~CC0201KRX7R8BB102  [C0201]  134.67 91.02 0 bottom
PC1210  C0201X7R102K250NTA+C0201X7R102K250NJA~~GRM033R71E102KA01D~~CC0201KRX7R8BB102  [C0201]  134.77 90.35 0 bottom
PC1211  C0201X5R105M6R3NTX~~CL03A105MQ3CSNH~~GRM033R60J105MEA2D~~JMK063ABJ105MP+JDK063ABJ105MP~~CC0201MRX5R5BB105  [C0201_0D4]  129.64 91.09 180 bottom
PC1212  C0402X5R106M6R3NTC~~CL05A106MQ5NUNC~~GRM155R60J106ME44~~JMK105CBJ106MV-F  [C0402_0D8]  129.65 88.17 180 bottom
PC1213  C0201X5R104M6R3NTA~~0201X104M6R3NT  [C0201]  131.77 93.44 270 bottom
PC1214  C0402X5R106M6R3NTC~~CL05A106MQ5NUNC~~GRM155R60J106ME44~~JMK105CBJ106MV-F  [C0402_0D8]  128.09 92.02 270 bottom
PC1215  CL10A226MQ8NRNC~~GRM188R60J226MEA0D~~JDK107BBJ226MA-T~~CC0603MRX5R5BB226  [C0603_L]  134.97 92.96 270 bottom
PC11258  CC0201KRX5R7BB104~~C0201X5R104M160NTA  [C0201]  174.38 50.49 180 bottom
PCS501  25TQC15MYFB  [NB_PCAP3528_2D0]  84.07 22.3 270 bottom
PCS502  EEFSX0D331ER  [NB_CT2_7D3X4D3X2]  97.41 31.19 180 bottom
PCS601  ACAH200S330E40  [NB_CT2_7D3X4D3X2]  123.09 10.84 180 bottom
PCS602  25TQC15MYFB  [NB_PCAP3528_2D0]  115.95 11 0 bottom
PCS604  EEFSX0E331ER  [NB_CT2_7D3X4D3X2]  116.08 31.42 0 bottom
PCS606  EEFSX0D331ER  [NB_CT2_7D3X4D3X2]  129.03 31.7 180 bottom
PCS801  ACAS2R0S331E09  [NB_CT2_7D3X4D3X2]  136.02 37.64 0 bottom
PCS802  ACAS2R0S331E09  [NB_CT2_7D3X4D3X2]  136.02 42.53 0 bottom
PCS804  25TQC15MYFB  [NB_PCAP3528_2D0]  162.3 34.05 180 bottom
PD904  LRC  LBAT54CWT1  [SOT-323_3_2X1D25X1]  49.38 61.29 0 bottom
PD906  LRC  LBAT54CWT1  [SOT-323_3_2X1D25X1]  51.89 61.29 0 bottom
PD907  LBAT54AWT1G  [NB_SOT323_2D4X2D2X1]  46.94 59.76 180 bottom
PDT1  PSBD1DF40V3H  [DIODE_2D75X1D8X1D1]  36.45 8.33 180 top
PDT2  PSBD1DF40V3H  [DIODE_2D75X1D8X1D1]  36.45 6.17 180 top
PESD104  ESD5401N-2/TR  [NB_DIODE2_1D05X0D65X0D55]  15.24 77.42 180 top
PESD105  ESD5451R-2/TR  [TVS2_1X0D5X0D6]  99.57 16.58 0 bottom
PESD106  ESD5342N-3/TR  [DFN1006_3_1X0D6X0D5_ESD5324N]  106.17 13.92 270 top
PESD107  PTVSHC3N15VU  [NB_ESD3_2D3X2D1X0D65]  86.68 7.88 0 bottom
PFB101  BLM18KG101TN1D  [NB_L0603]  17.27 76.4 270 top
PFB102  BLM18KG101TN1D  [NB_L0603]  18.67 76.4 270 top
PJ101  50458-00801-003~#~50458-00801-001  [NB_BAT8_21X6D4X2D26_2]  99.79 9.34 180 bottom
PJ102  30706-11702-001  [NB_DC5_12D2X6D8X5D2]  4.86 78.09 90 bottom
PL101  TMPC1003H-2R2MG-D  [NB_L2_11D5X10D3X3]  66.61 16.08 0 bottom
PL102  MAPM0630F-1R0M20-LF  [NB_L2_7D3X6D8X3]  66.61 16.08 0 bottom
PL201  MAPM0630F-1R0M20-LF  [NB_L2_7D3X6D8X3]  40.89 47.39 180 bottom
PL301  MAPM0630F-1R0M20-LF  [NB_L2_7D3X6D8X3]  40.89 55.12 180 bottom
PL401  MHCHL252010D-1R0M-QE  [L2520_1D05]  42.92 60.53 0 bottom
PL402  MPIA252010E1R0M-LF  [L2520_1D05]  30.35 61.03 270 bottom
PL501  TMPC0603HT-R22MG-2R307-EW  [NB_L2_7D3X6D8X3]  92.33 24.2 90 bottom
PL601  TMPC0603HT-R22MG-2R307-EW  [NB_L2_7D3X6D8X3]  127.76 25.47 180 bottom
PL602  TMPC0603HT-R22MG-2R307-EW  [NB_L2_7D3X6D8X3]  118.36 25.47 0 bottom
PL701  MAPM0630F-R68M20-LF  [NB_L2_7D3X6D8X3]  51.92 83.54 90 bottom
PL702  WPN201610HS4R7MT~~ DFE2016MET-4R7M=P2~~CIGW201610GL4R7MLE  [L2016_1]  47.04 85.32 90 bottom
PL802  MHCI06030-R36M-R8A3R05  [NB_L2_7D3X6D8X3]  145.29 45.39 180 bottom
PL803  MHCI06030-R36M-R8A3R05  [NB_L2_7D3X6D8X3]  145.29 38.12 180 bottom
PL1101  MAPM0630F-R68M20-LF  [NB_L2_7D3X6D8X3]  176.99 44.32 90 bottom
PQ101  AONR21357  [NB_SON5_3D1X3D1X0D9]  80.52 14.55 0 bottom
PQ103  PK6D0BA  [NB_DFN5_5D55X5D2X1]  56.7 19.82 180 bottom
PQ105  AON7534  [NB_SON5_3D1X3D1X0D9]  56.64 14.42 90 bottom
PQ107  AON7534  [NB_SON5_3D1X3D1X0D9]  76.07 16.71 90 bottom
PQ108  AON7534  [NB_SON5_3D1X3D1X0D9]  75.82 12.65 180 bottom
PQ110  AONR21357  [NB_SON5_3D1X3D1X0D9]  20.52 65.15 0 bottom
PQ111  AONR21357  [NB_SON5_3D1X3D1X0D9]  20.52 69.97 180 bottom
PQ112  2N7002~~2N7002LT1G~~L2N7002LT1G  [SOT-23_3_2D9X1D3X1D11]  24.43 68.3 0 bottom
PQ114  2N7002~~2N7002LT1G~~L2N7002LT1G  [SOT-23_3_2D9X1D3X1D11]  24.38 64.84 180 top
PQ501  PK6D0BA  [NB_DFN5_5D55X5D2X1]  86.99 16.58 270 bottom
PQ502  PK664BA  [NB_DFN5_5D55X5D2X1]  93.85 16.58 270 bottom
PQ601  PK6D0BA  [NB_DFN5_5D55X5D2X1]  119 18.36 0 bottom
PQ602  PK664BA  [NB_DFN5_5D55X5D2X1]  113.28 18.36 180 bottom
PQ603  PK664BA  [NB_DFN5_5D55X5D2X1]  132.71 18.87 270 bottom
PQ604  PK6D0BA  [NB_DFN5_5D55X5D2X1]  125.98 18.74 270 bottom
PQ801  PKC46DY  [NB_MOS10_6X5X0D8]  152.91 46.35 0 bottom
PQ802  PKC46DY  [NB_MOS10_6X5X0D8]  152.86 37.77 180 bottom
PQ901  WNM2046-3/TR  [DFN1006_3_1X0D6X0D5]  68.45 25.6 180 bottom
PQ902  WNM2046-3/TR  [DFN1006_3_1X0D6X0D5]  67.18 25.6 0 bottom
PR1  0201WMJ0000TCE+0201WMJ0000TJE~~MCR006YRTJ000~~RC0201JR-070RL+RC0201JR-130RL~~WR02X000PAL  [R0201]  133.12 82.68 0 top
PR105  0603WAF220KT5E~~RC0603FR-072R2L  [R0603]  70.61 22.17 0 bottom
PR106  LR122WF500NT2E~~PA2512FKF7W0R005E~~MFL12KR005FT  [NB_RTC0805]  51.94 21.92 0 bottom
PR107  0402WGJ0100TCE~~RC1005J100CS~~RM04JTN100~~RC0402JR-0710RL  [R0402]  52.32 14.42 0 bottom
PR108  0402WGJ0100TCE~~RC1005J100CS~~RM04JTN100~~RC0402JR-0710RL  [R0402]  52.32 15.31 0 bottom
PR110  0402WGJ0100TCE~~RC1005J100CS~~RM04JTN100~~RC0402JR-0710RL  [R0402]  52.14 11.38 180 bottom
PR111  0201WMF3303TCE~~MCR006YRTF3303~~RC0201FR-07330KL~~WR02X3303FAL  [R0201]  51.06 12.37 270 bottom
PR112  RC0201FR-07220KL~~0201WMF0224TCE  [R0201]  51.88 12.62 180 bottom
PR115  0402WGF4022TCE~~RC0402FR-0740K2L  [R0402]  44.18 10.69 90 bottom
PR116  0201WMF1002TCE~~MCR006YRTF1002~~WR02X1002FAL~~RC0201FR-0710KL  [R0201]  43.32 11.61 90 bottom
PR117  MCR006YRTF1003~~RC0201FR-07100KL~~WR02X1003FAL~~0201WMF1003TCE  [R0201]  43.01 13.13 0 bottom
PR120  0201WMF8202TCE~~MCR006YRTF8202~~RC0201FR-0782KL~~WR02X8202FAL  [R0201]  43.01 13.74 180 bottom
PR121  RC0201FR-07137KL~~0201WMF1373TCE  [R0201]  49.87 10.49 90 bottom
PR122  0201WMJ0100TCE~~MCR006YRTJ100~~RC0201JR-0710RL~~WR02X100 JAL  [R0201]  43.04 14.35 0 bottom
PR123  0201WMJ0100TCE~~MCR006YRTJ100~~RC0201JR-0710RL~~WR02X100 JAL  [R0201]  43.04 14.86 0 bottom
PR125  RC1608J000CS~~RC0603JR-070RL~~RM06JTN0~~0603WAJ0000T5E  [R0603]  44.07 18.36 90 bottom
PR126  RC0805FR-071R5L~~0805W8F150KT5E~~RM10FTN1R50  [R0805]  52 18.51 0 bottom
PR128  RC1608J000CS~~RC0603JR-070RL~~RM06JTN0~~0603WAJ0000T5E  [R0603]  48.06 18.64 270 bottom
PR129  RC0201FR-07100RL~~WR02X1000FAL~~0201WMF1000TCE~~MCR006YRTF1000  [R0201]  104.39 13.66 180 top
PR130  0201WMJ0000TCE+0201WMJ0000TJE~~MCR006YRTJ000~~RC0201JR-070RL+RC0201JR-130RL~~WR02X000PAL  [R0201]  48.13 10.49 90 bottom
PR131  0201WMF1002TCE+0201WMF1002TEE~~MCR006YRTF1002~~WR02X1002FAL~~RC0201FR-0710KL  [R0201]  53.47 11.38 180 bottom
PR132  RC0805FR-7W2R2L~~0805W4F220KT5E~~RMH10FT2R20  [R0805]  18.41 80.59 180 top
PR133  RC0805FR-7W2R2L~~0805W4F220KT5E~~RMH10FT2R20  [R0805]  18.41 78.81 180 top
PR134  0201WMJ0472TCE~~MCR006YRTJ472~~RC0201JR-074K7L~~WR02X472JAL  [R0201]  157.17 23.09 180 top
PR135  RC0201FR-07100RL~~WR02X1000FAL~~0201WMF1000TCE~~MCR006YRTF1000  [R0201]  104.39 14.17 180 top
PR136  WR02X102JAL~~RC0201JR-071KL~~0201WMJ0102TCE+0201WMJ0102TJE~~MCR006YRTJ102  [R0201]  99.95 15.57 270 bottom
PR137  0201WMJ0104TCE~~MCR006YRTJ104~~RC0201JR-07100KL~~WR02X104JAL  [R0201]  99.31 15.57 90 bottom
PR138  0201WMJ0105TCE~~MCR006YRTJ105~~RC0201JR-071ML~~WR02X105JAL  [R0201]  53.47 10.74 0 bottom
PR141  0201WMJ0104TCE~~MCR006YRTJ104~~RC0201JR-07100KL~~WR02X104JAL  [R0201]  22.43 67.51 90 top
PR160  0603WAF220KT5E~~RC0603FR-072R2L  [R0603]  63.37 22.17 180 bottom
PR161  0201WMJ0000TCE+0201WMJ0000TJE~~MCR006YRTJ000~~RC0201JR-070RL+RC0201JR-130RL~~WR02X000PAL  [R0201]  46.23 10.49 90 bottom
PR162  RC0201FR-07100RL~~WR02X1000FAL~~0201WMF1000TCE~~MCR006YRTF1000  [R0201]  48.86 10.49 90 bottom
PR163  0201WMJ0472TCE~~MCR006YRTJ472~~RC0201JR-074K7L~~WR02X472JAL  [R0201]  158.34 23.49 90 top
PR164  SHUNT_LOCAL  [SHUNT_0402]  43.33 15.52 90 bottom
PR165  PE1206FKM470R01Z~~MS061WF100MT5E  [NB_RTC1206_0D9]  82.42 10.87 0 bottom
PR166  0201WMJ0104TCE~~MCR006YRTJ104~~RC0201JR-07100KL~~WR02X104JAL  [R0201]  25.4 68.65 180 top
PR167  0201WMJ0513TCE~~MCR006YRTJ513~~RC0201JR-0751KL~~WR02X513JAL  [R0201]  25.45 67.23 180 top
PR168  0201WMJ0103TCE+0201WMJ0103TJE~~MCR006YRTJ103~~RC0201JR-0710KL~~WR02X103JAL  [R0201]  24.03 68.98 90 top
PR169  0201WMJ0203TCE~~MCR006YRTJ203~~RC0201JR-0720KL~~WR02X203JAL  [R0201]  26.54 63.19 0 top
PR170  0805W8J0000T5E~~RC0805JR-070RL~~RM10JTN0  [R0805]  20.39 67.64 270 top
PR185  WR02X102JAL~~RC0201JR-071KL~~0201WMJ0102TCE+0201WMJ0102TJE~~MCR006YRTJ102  [R0201]  23.06 67.51 270 top
PR186  0201WMJ0104TCE~~MCR006YRTJ104~~RC0201JR-07100KL~~WR02X104JAL  [R0201]  24.59 68.98 270 top
PR187  WR02X102JAL~~RC0201JR-071KL~~0201WMJ0102TCE+0201WMJ0102TJE~~MCR006YRTJ102  [R0201]  13.08 72.59 0 bottom
PR188  0201WMJ0106TCE//RC0201JR-0710ML~~RC0201JR-0710ML  [R0201]  23.26 65.71 90 bottom
PR201  RC0603FR-0710RL~~0603WAF100JT5E  [R0603]  46.1 44.04 270 bottom
PR202  0402WGJ0000TCE+0402WGJ0000TJE~~RC1005J000CS~~RC0402JR-070RL+RC0402JR-130RL~~RM04JTN0  [R0402_0D65]  50.29 43.89 90 bottom
PR203  0201WMF1001TCE+0201WMF1001TEE~~MCR006YRTF1001~~RC0201FR-071KL~~WR02X1001FAL  [R0201]  49.45 44.14 270 bottom
PR204  0201WMF1001TCE~~MCR006YRTF1001~~RC0201FR-071KL~~WR02X1001FAL  [R0201]  47.01 43.69 270 bottom
PR205  0201WMJ0105TCE~~MCR006YRTJ105~~RC0201JR-071ML~~WR02X105JAL  [R0201]  49.4 46.17 0 top
PR301  RC0603FR-0710RL~~0603WAF100JT5E  [R0603]  46.48 51.56 270 bottom
PR302  0201WMF1001TCE+0201WMF1001TEE~~MCR006YRTF1001~~RC0201FR-071KL~~WR02X1001FAL  [R0201]  50.16 52.02 270 bottom
PR305  0201WMJ0000TCE+0201WMJ0000TJE~~MCR006YRTJ000~~RC0201JR-070RL+RC0201JR-130RL~~WR02X000PAL  [R0201]  51.66 52.4 90 bottom
PR306  0201WMF1001TCE~~MCR006YRTF1001~~RC0201FR-071KL~~WR02X1001FAL  [R0201]  49.27 52.17 0 bottom
PR307  0201WMJ0104TCE~~MCR006YRTJ104~~RC0201JR-07100KL~~WR02X104JAL  [R0201]  51.1 52.4 90 bottom
PR401  0201WMJ0000TCE+0201WMJ0000TJE~~MCR006YRTJ000~~RC0201JR-070RL+RC0201JR-130RL~~WR02X000PAL  [R0201]  37.21 61.54 270 bottom
PR402  0201WMJ0104TCE~~MCR006YRTJ104~~RC0201JR-07100KL~~WR02X104JAL  [R0201]  37.97 60.78 180 bottom
PR403  0201WMF3302TCE+0201WMF3302TEE~~MCR006YRTF3302~~RC0201FR-0733KL~~WR02X3302FAL  [R0201]  38.23 60.02 90 bottom
PR404  res  [R0201]  37.97 59.26 0 bottom
PR410  MCR006YRTF1003~~RC0201FR-07100KL~~WR02X1003FAL~~0201WMF1003TCE+0201WMF1003TEE  [R0201]  35.81 64.34 180 bottom
PR411  0201WMJ0104TCE~~MCR006YRTJ104~~RC0201JR-07100KL~~WR02X104JAL  [R0201]  33.15 65.22 180 bottom
PR412  MCR006YRTF1003~~RC0201FR-07100KL~~WR02X1003FAL~~0201WMF1003TCE+0201WMF1003TEE  [R0201]  35.81 63.83 0 bottom
PR413  SHUNT_LOCAL  [SHUNT_0402]  36.12 61.31 0 bottom
PR414  SHUNT_LOCAL  [SHUNT_0201]  37.21 63.32 180 bottom
PR415  0201WMJ0104TCE~~MCR006YRTJ104~~RC0201JR-07100KL~~WR02X104JAL  [R0201]  37.21 63.83 0 bottom
PR501  0201WMF1002TCE~~MCR006YRTF1002~~WR02X1002FAL~~RC0201FR-0710KL  [R0201]  72.41 25.6 90 bottom
PR502  0201WMF1002TCE~~MCR006YRTF1002~~WR02X1002FAL~~RC0201FR-0710KL  [R0201]  72.39 26.74 270 bottom
PR503  0201WMF1002TCE~~MCR006YRTF1002~~WR02X1002FAL~~RC0201FR-0710KL  [R0201]  73.66 25.6 90 bottom
PR504  0201WMF1002TCE~~MCR006YRTF1002~~WR02X1002FAL~~RC0201FR-0710KL  [R0201]  73.66 26.74 270 bottom
PR505  RC1608J000CS~~RC0603JR-070RL~~RM06JTN0~~0603WAJ0000T5E  [R0603_1]  72.52 30.17 90 bottom
PR506  RC1608J000CS~~RC0603JR-070RL~~RM06JTN0~~0603WAJ0000T5E  [R0603_1]  79.25 23.44 90 bottom
PR507  RC1608J000CS~~RC0603JR-070RL~~RM06JTN0~~0603WAJ0000T5E  [R0603_1]  73.79 30.17 270 bottom
PR508  MCR006YRTF1003~~RC0201FR-07100KL~~WR02X1003FAL~~0201WMF1003TCE  [R0201]  73.02 25.6 90 bottom
PR509  0201WMF2203TCE +  0201WMF2203TEE~~RC0201FR-07220KL  [R0201]  75.44 29.66 270 bottom
PR510  RC1608J000CS~~RC0603JR-070RL~~RM06JTN0~~0603WAJ0000T5E  [R0603_1]  88.01 12.77 180 bottom
PR511  MCR006YRTF1003~~RC0201FR-07100KL~~WR02X1003FAL~~0201WMF1003TCE  [R0201]  73.02 26.74 270 bottom
PR513  MCR006YRTF1003~~RC0201FR-07100KL~~WR02X1003FAL~~0201WMF1003TCE  [R0201]  76.96 29.54 90 bottom
PR514  0402WGJ0000TCE+0402WGJ0000TJE~~RC1005J000CS~~RC0402JR-070RL+RC0402JR-130RL~~RM04JTN0  [R0402_0D65]  78.1 30.44 0 top
PR515  0402WGJ0000TCE+0402WGJ0000TJE~~RC1005J000CS~~RC0402JR-070RL+RC0402JR-130RL~~RM04JTN0  [R0402_0D65]  78.1 29.54 0 top
PR516  RC0201FR-07357RL~~0201WMF3570TCE+0201WMF3570TEE  [R0201]  81.39 30.35 0 top
PR517  RC0402FR-071KL~~0402WGF1001TCE  [R0402]  81.53 29.64 180 top
PR518  0402WGJ0101TCE~~RC0402JR-07100RL~~RM04JTN101~~RC1005J101CS  [R0402]  81.41 29.41 90 bottom
PR519  MCR006YRTF1003~~RC0201FR-07100KL~~WR02X1003FAL~~0201WMF1003TCE  [R0201]  80.9 24.97 0 bottom
PR520  0402WGJ0000TCE+0402WGJ0000TJE~~RC1005J000CS~~RC0402JR-070RL+RC0402JR-130RL~~RM04JTN0  [R0402_0D65]  79.37 30.05 90 top
PR521  MCR006YRTF1003~~RC0201FR-07100KL~~WR02X1003FAL~~0201WMF1003TCE  [R0201]  79.75 24.97 0 bottom
PR522  0201WMF1002TCE~~MCR006YRTF1002~~WR02X1002FAL~~RC0201FR-0710KL  [R0201]  79.88 28.78 180 bottom
PR523  0201WMF1401TCE+0201WMF1401TEE~~RC0201FR-071K4L  [R0201]  80.77 28.01 90 bottom
PR524  WR02X1692FAL~~RC0201FR-0716K9L~~MCR006YRTF1692~~0201WMF1692TCE+0201WMF1692TEE  [R0201]  79.88 28.27 0 bottom
PR525  0201WMJ0000TCE+0201WMJ0000TJE~~MCR006YRTJ000~~RC0201JR-070RL+RC0201JR-130RL~~WR02X000PAL  [R0201]  79.88 25.75 0 bottom
PR526  0201WMJ0000TCE+0201WMJ0000TJE~~MCR006YRTJ000~~RC0201JR-070RL+RC0201JR-130RL~~WR02X000PAL  [R0201]  79.88 26.31 0 bottom
PR527  0402WGJ0101TCE~~RC0402JR-07100RL~~RM04JTN101~~RC1005J101CS  [R0402]  80.02 27 180 bottom
PR528  0402WGJ0000TCE+0402WGJ0000TJE~~RC1005J000CS~~RC0402JR-070RL+RC0402JR-130RL~~RM04JTN0  [R0402_0D65]  70.97 26.62 0 bottom
PR529  0402WGJ0000TCE+0402WGJ0000TJE~~RC1005J000CS~~RC0402JR-070RL+RC0402JR-130RL~~RM04JTN0  [R0402_0D65]  70.97 25.73 0 bottom
PR530  0402WGJ0000TCE+0402WGJ0000TJE~~RC1005J000CS~~RC0402JR-070RL+RC0402JR-130RL~~RM04JTN0  [R0402_0D65]  72.52 28.14 0 bottom
PR531  0603WAJ047JT5E~~RC0603JR-074R7L  [R0603]  73.15 23.19 180 bottom
PR532  0402WGJ0392TCE~~RC1005J392CS~~RC0402JR-073K9L~~RM04JTN392  [R0402]  81.53 31.06 0 top
PR601  0402WGJ062JTCE/RC0402JR-076R2L  [R0402]  99.5 26.49 180 top
PR602  0402WGJ022JTCE~~RC1005J2R2CS~~RC0402JR-072R2L~~RM04JTN2R2  [R0402]  106.81 17.22 90 bottom
PR603  0603WAF220KT5E~~RC0603FR-072R2L  [R0603]  108.96 23.01 180 top
PR604  0201WMJ0000TCE+0201WMJ0000TJE~~MCR006YRTJ000~~RC0201JR-070RL+RC0201JR-130RL~~WR02X000PAL  [R0201]  109.09 17.22 90 bottom
PR605  0603WAF220KT5E~~RC0603FR-072R2L  [R0603]  108.96 18.87 0 top
PR606  RC1608J000CS~~RC0603JR-070RL~~RM06JTN0~~0603WAJ0000T5E  [R0603_1]  129.4 14.81 180 bottom
PR607  0402WGJ0101TCE~~RC0402JR-07100RL~~RM04JTN101~~RC1005J101CS  [R0402]  107.69 25.96 270 top
PR608  RC0402JR-073R9L/0402WGJ039JTCE  [R0402]  101.09 22.55 180 bottom
PR609  res  [R0201]  102.36 27.38 90 top
PR610  res  [R0201]  103.88 27.38 90 top
PR611  res  [R0201]  104.39 27.38 90 top
PR612  0201WMF1502TCE+0201WMF1502TEE~~MCR006YRTF1502~~RC0201FR-0715KL~~WR02X1502FAL  [R0201]  105.54 16.46 180 bottom
PR613  0603WAF220KT5E~~RC0603FR-072R2L  [R0603]  109.22 25.85 0 top
PR614  RC1608J000CS~~RC0603JR-070RL~~RM06JTN0~~0603WAJ0000T5E  [R0603_1]  119.51 22.43 0 top
PR615  RC0201FR-07100RL~~WR02X1000FAL~~0201WMF1000TCE+0201WMF1000TEE~~MCR006YRTF1000  [R0201]  105.54 16.96 0 bottom
PR616  res  [R0201]  102.36 25.92 90 top
PR617  res  [R0201]  103.88 25.92 90 top
PR618  RC0201JR-072K2L~~MCR006YRTJ222~~WR02X222 JAL~~0201WMJ0222TCE+0201WMJ0222TJE  [R0201]  104.39 25.92 90 top
PR619  MCR006YRTF1103~~0201WMF1103TCE~~WR02X1103FAL~~RC0201FR-07110KL  [R0201]  105.03 17.6 180 bottom
PR620  res  [R0201]  102.87 25.92 270 top
PR621  RC0201FR-075K6L~~0201WMF5601TCE+0201WMF5601TEE  [R0201]  103.38 25.92 270 top
PR622  0201WMF2202TCE+0201WMF2202TEE~~RC0201FR-0722KL~~MCR006YRTF2202~~WR02X2202FAL  [R0201]  104.9 25.92 270 top
PR623  RC0201FR-0718KL~~0201WMF1802TCE+0201WMF1802TEE  [R0201]  104.39 16.96 0 bottom
PR624  res  [R0201]  102.87 27.38 270 top
PR625  RC0201FR-07357RL~~0201WMF3570TCE+0201WMF3570TEE  [R0201]  103.38 27.38 270 top
PR626  res  [R0201]  104.9 27.38 270 top
PR627  0201WMF1500TCE+0201WMF1500TEE~~MCR006YRTF1500~~RC0201FR-07150RL  [R0201]  104.39 16.43 180 bottom
PR628  0201WMF1002TCE~~MCR006YRTF1002~~WR02X1002FAL~~RC0201FR-0710KL  [R0201]  109.09 17.22 270 top
PR629  0402WGJ0000TCE+0402WGJ0000TJE~~RC1005J000CS~~RC0402JR-070RL+RC0402JR-130RL~~RM04JTN0  [R0402_0D65]  98.42 19.89 180 bottom
PR630  0402WGJ0101TCE~~RC0402JR-07100RL~~RM04JTN101~~RC1005J101CS  [R0402]  98.42 19 0 bottom
PR631  0201WMF1002TCE~~MCR006YRTF1002~~WR02X1002FAL~~RC0201FR-0710KL  [R0201]  101.73 27.38 270 top
PR632  0201WMF1002TCE~~MCR006YRTF1002~~WR02X1002FAL~~RC0201FR-0710KL  [R0201]  101.22 20.34 180 top
PR633  0201WMF2102TCE+0201WMF2102TEE~~RC0201FR-0721KL  [R0201]  101.22 18.49 0 top
